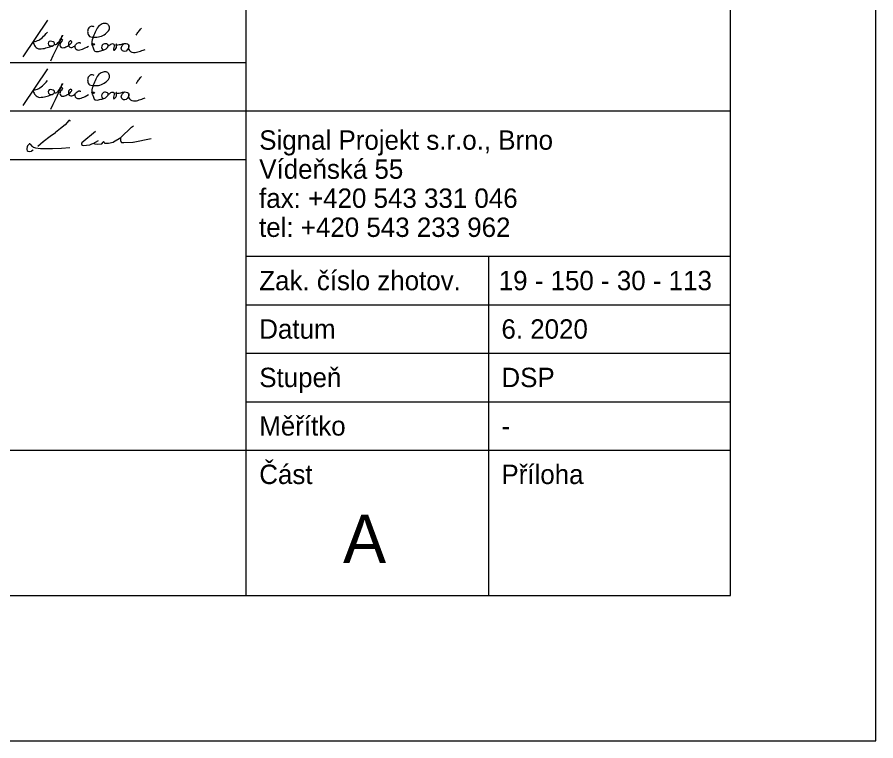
# Model space of a CAD drawing. Extents: x -790471 to -790261, y -984072 to -983775.
# Drawn here: x -790349.2 to -790260.6, y -984071.6 to -983996.9 of the extents above; entities that cross this region are included whole.
import ezdxf

# ---------------------------------------------------------------- set-up
doc = ezdxf.new("R2010")
doc.units = 0
for name, color, linetype in [('Deska žb', 7, 'Continuous'), ('Podpisy', 7, 'Continuous'), ('Ramečky', 7, 'Continuous'), ('Rámečky-tisk', 7, 'Continuous'), ('Text', 7, 'Continuous'), ('Text barevný', 7, 'Continuous')]:
    doc.layers.add(name, color=color, linetype=linetype)

# ---------------------------------------------------------------- blocks, each defined once
blk = doc.blocks.new('Lukášek')
at = {"layer": 'Deska žb'}
for points in [[(-658, 623), (-799, 512)], [(-538, 757), (-656, 625)], [(-526, 763), (-532, 761)], [(-502, 743), (-503, 750)], [(1060, 236), (1392, 554)], [(1393, 555), (1452, 601)], [(-1120, 270), (-1334, 99)], [(-949, 386), (-1119, 271)], [(-800, 511), (-947, 387)], [(277, 422), (-140, 71)], [(-1810, -20), (-1764, 37)], [(-1741, 39), (-1734, 34)], [(-1733, 32), (-1676, -31)], [(-1334, 99), (-1493, -40)], [(-146, 58), (-146, 41)], [(-146, 38), (-141, 12)], [(0, 0), (116, 16)], [(120, 17), (203, 49)], [(205, 50), (283, 92)], [(244, 59), (250, 49)], [(261, 42), (331, 30)], [(284, 93), (373, 148)], [(335, 30), (465, 39)], [(476, 45), (519, 96)], [(546, 94), (559, 68)], [(574, 60), (681, 63)], [(685, 63), (829, 98)], [(833, 100), (1057, 233)], [(1056, 231), (1056, 130)], [(1058, 121), (1075, 95)], [(1086, 88), (1147, 79)], [(1150, 79), (1434, 92)], [(1437, 93), (1997, 211)], [(-1825, -119), (-1813, -28)], [(-1809, -179), (-1825, -126)], [(-1757, -200), (-1797, -190)], [(-1700, -189), (-1749, -201)], [(-1634, -152), (-1695, -187)], [(-1672, -34), (-1636, -56)], [(-1633, -57), (-1570, -82)], [(-1567, -83), (-1418, -106)], [(-1415, -106), (-1252, -106), (-1041, -106)], [(-1040, -106), (-770, -93)], [(-769, -92), (-512, -66)], [(-127, -2), (-88, -6)], [(-85, -7), (-1, 0)]]:
    blk.add_lwpolyline(points, dxfattribs=at)
for centre, start, end in [((-669, 636), 308.3333, 317.9357), ((-525, 746), 113.9625, 137.9357), ((-519, 748), 6.3402, 113.9625), ((1403, 542), 127.875, 133.8427), ((-1110, 257), 123.9436, 128.6598), ((-958, 399), 303.9436, 310.1792), ((-789, 499), 128.3333, 130.1792), ((-1751, 26), 50.1944, 140.7106), ((-1745, 21), 41.9872, 50.1944), ((-1324, 86), 128.6598, 131.1859), ((-129, 58), 130.156, 180), ((-129, 41), 180, 189.4623), ((-125, 15), 189.4623, 262.875), ((-2, 16), 274.3987, 277.9072), ((114, 32), 277.9072, 291.0375), ((197, 64), 291.0375, 298.4429), ((264, 58), 210.9638, 260.5377), ((275, 107), 298.4429, 302.1957), ((334, 46), 260.5377, 274.0856), ((463, 55), 274.0856, 320.4403), ((531, 86), 27.8973, 140.4403), ((574, 76), 207.8973, 271.5911), ((681, 79), 271.5911, 283.7363), ((825, 114), 283.7363, 300.7189), ((1072, 130), 180, 212.4712), ((1049, 247), 300.7189, 313.8427), ((1089, 104), 212.4712, 261.8699), ((1149, 96), 261.8699, 272.6324), ((1433, 109), 272.6324, 281.9566), ((-1809, -121), 172.4054, 196.6992), ((-1797, -30), 140.7106, 172.4054), ((-1793, -175), 196.6992, 255.9638), ((-1753, -184), 255.9638, 283.2405), ((-1703, -173), 283.2405, 300.0686), ((-1664, -20), 221.9872, 239.7436), ((-1627, -41), 239.7436, 248.1986), ((-1564, -67), 248.1986, 261.3475), ((-1415, -89), 261.3475, 270), ((-1041, -89), 270, 272.7927), ((-771, -76), 272.7927, 275.856), ((-86, 10), 262.875, 274.3987)]:
    blk.add_arc(centre, 16.5, start, end, dxfattribs=at)

msp = doc.modelspace()

# ---------------------------------------------------------------- linework, layer by layer
for p, q in [((-790346.115, -983997.244), (-790348.663, -984001.025)), ((-790346.115, -984002.244), (-790348.663, -984006.025))]:
    msp.add_line(p, q)
for points in [[(-790341.279, -983997.932), (-790341.403, -983997.883), (-790341.624, -983997.795), (-790341.944, -983998.102), (-790341.988, -983998.492), (-790341.839, -983998.977), (-790341.182, -983999.004), (-790340.523, -983998.931), (-790339.963, -983998.552), (-790339.627, -983998.121), (-790339.743, -983997.755), (-790340.022, -983997.524), (-790340.448, -983997.591), (-790340.922, -983997.862), (-790341.175, -983998.482), (-790341.471, -983999.088), (-790341.534, -983999.538), (-790341.56, -983999.725)], [(-790336.941, -983998.767), (-790336.885, -983998.674), (-790336.731, -983998.417), (-790336.529, -983998.195), (-790336.4, -983998.053)], [(-790347.607, -983999.459), (-790347.471, -983999.438), (-790347.152, -983999.39), (-790346.617, -983999.051), (-790346.31, -983998.682), (-790346.12, -983998.454)], [(-790345.367, -983999.701), (-790345.331, -983999.727), (-790345.071, -983999.918), (-790344.193, -983997.983), (-790345.101, -983999.96), (-790345.793, -984001.466)], [(-790347.607, -983999.459), (-790347.564, -983999.581), (-790347.469, -983999.848), (-790347.105, -984000.265), (-790346.386, -984000.146), (-790345.871, -983999.982), (-790345.36, -983999.82), (-790345.358, -983999.503), (-790345.652, -983999.408), (-790345.966, -983999.372), (-790346.085, -983999.642), (-790345.908, -983999.896), (-790345.702, -983999.894), (-790345.586, -983999.893)], [(-790344.735, -983999.177), (-790344.686, -983999.177), (-790344.387, -983999.177), (-790344.935, -983999.693), (-790344.696, -984000.168), (-790344.167, -983999.993), (-790343.885, -983999.83), (-790343.466, -983999.455), (-790343.798, -983999.276), (-790344.006, -983999.671), (-790343.862, -984000.105), (-790343.352, -983999.997), (-790343.146, -983999.688), (-790342.94, -983999.53), (-790342.757, -983999.518), (-790342.732, -983999.588), (-790342.716, -983999.63)], [(-790343.286, -983999.868), (-790343.285, -983999.962), (-790343.284, -984000.133), (-790343.045, -984000.359), (-790342.5, -984000.261), (-790342.128, -984000.055), (-790341.867, -983999.911)], [(-790341.56, -983999.725), (-790341.52, -983999.687), (-790341.438, -983999.606), (-790341.14, -983999.722), (-790341.419, -983999.825), (-790341.509, -983999.807), (-790341.521, -983999.804)], [(-790341.521, -983999.804), (-790341.474, -983999.87), (-790341.357, -984000.031), (-790341.303, -984000.538), (-790340.687, -984000.428), (-790340.261, -984000.313), (-790339.98, -984000.166), (-790339.692, -983999.742), (-790340.293, -983999.598), (-790340.517, -983999.901), (-790340.533, -984000.2), (-790340.397, -984000.281), (-790340.337, -984000.317)], [(-790339.858, -983999.773), (-790339.824, -983999.81), (-790339.761, -983999.877), (-790339.618, -983999.774), (-790339.527, -983999.643), (-790339.088, -983999.646), (-790339.415, -984000.465), (-790338.967, -984000.238), (-790338.963, -983999.549), (-790339.087, -983999.805), (-790339.029, -983999.851), (-790338.865, -983999.772), (-790338.538, -983999.749), (-790338.168, -983999.582), (-790337.514, -983999.74), (-790337.986, -984000.599), (-790338.522, -984000.346), (-790338.486, -983999.912), (-790338.288, -983999.74), (-790338.187, -983999.652)], [(-790337.732, -983999.834), (-790337.744, -984000.022), (-790337.77, -984000.434), (-790337.02, -984000.633), (-790336.498, -984000.411), (-790336.141, -984000.288), (-790336.021, -984000.247)], [(-790341.279, -984002.932), (-790341.403, -984002.883), (-790341.624, -984002.795), (-790341.944, -984003.102), (-790341.988, -984003.492), (-790341.839, -984003.977), (-790341.182, -984004.004), (-790340.523, -984003.931), (-790339.963, -984003.552), (-790339.627, -984003.121), (-790339.743, -984002.755), (-790340.022, -984002.524), (-790340.448, -984002.591), (-790340.922, -984002.862), (-790341.175, -984003.482), (-790341.471, -984004.088), (-790341.534, -984004.538), (-790341.56, -984004.725)], [(-790347.607, -984004.459), (-790347.471, -984004.438), (-790347.152, -984004.39), (-790346.617, -984004.051), (-790346.31, -984003.682), (-790346.12, -984003.454)], [(-790336.941, -984003.767), (-790336.885, -984003.674), (-790336.731, -984003.417), (-790336.529, -984003.195), (-790336.4, -984003.053)], [(-790347.607, -984004.459), (-790347.564, -984004.581), (-790347.469, -984004.848), (-790347.105, -984005.265), (-790346.386, -984005.146), (-790345.871, -984004.982), (-790345.36, -984004.82), (-790345.358, -984004.503), (-790345.652, -984004.408), (-790345.966, -984004.372), (-790346.085, -984004.642), (-790345.908, -984004.896), (-790345.702, -984004.894), (-790345.586, -984004.893)], [(-790345.367, -984004.701), (-790345.331, -984004.727), (-790345.071, -984004.918), (-790344.193, -984002.983), (-790345.101, -984004.96), (-790345.793, -984006.466)], [(-790344.735, -984004.177), (-790344.686, -984004.177), (-790344.387, -984004.177), (-790344.935, -984004.693), (-790344.696, -984005.168), (-790344.167, -984004.993), (-790343.885, -984004.83), (-790343.466, -984004.455), (-790343.798, -984004.276), (-790344.006, -984004.671), (-790343.862, -984005.105), (-790343.352, -984004.997), (-790343.146, -984004.688), (-790342.94, -984004.53), (-790342.757, -984004.518), (-790342.732, -984004.588), (-790342.716, -984004.63)], [(-790343.286, -984004.868), (-790343.285, -984004.962), (-790343.284, -984005.133), (-790343.045, -984005.359), (-790342.5, -984005.261), (-790342.128, -984005.055), (-790341.867, -984004.911)], [(-790341.56, -984004.725), (-790341.52, -984004.687), (-790341.438, -984004.606), (-790341.14, -984004.722), (-790341.419, -984004.825), (-790341.509, -984004.807), (-790341.521, -984004.804)], [(-790341.521, -984004.804), (-790341.474, -984004.87), (-790341.357, -984005.031), (-790341.303, -984005.538), (-790340.687, -984005.428), (-790340.261, -984005.313), (-790339.98, -984005.166), (-790339.692, -984004.742), (-790340.293, -984004.598), (-790340.517, -984004.901), (-790340.533, -984005.2), (-790340.397, -984005.281), (-790340.337, -984005.317)], [(-790339.858, -984004.773), (-790339.824, -984004.81), (-790339.761, -984004.877), (-790339.618, -984004.774), (-790339.527, -984004.643), (-790339.088, -984004.646), (-790339.415, -984005.465), (-790338.967, -984005.238), (-790338.963, -984004.549), (-790339.087, -984004.805), (-790339.029, -984004.851), (-790338.865, -984004.772), (-790338.538, -984004.749), (-790338.168, -984004.582), (-790337.514, -984004.74), (-790337.986, -984005.599), (-790338.522, -984005.346), (-790338.486, -984004.912), (-790338.288, -984004.74), (-790338.187, -984004.652)], [(-790337.732, -984004.834), (-790337.744, -984005.022), (-790337.77, -984005.434), (-790337.02, -984005.633), (-790336.498, -984005.411), (-790336.141, -984005.288), (-790336.021, -984005.247)]]:
    msp.add_open_spline(points, degree=3)
at = {"layer": 'Ramečky'}
for p, q in [((-790325.592, -984056.601), (-790325.592, -983971.601)), ((-790275.592, -984056.601), (-790275.592, -983971.601)), ((-790455.592, -984001.601), (-790325.592, -984001.601)), ((-790455.592, -984006.601), (-790325.592, -984006.601)), ((-790455.592, -984011.601), (-790325.592, -984011.601)), ((-790325.592, -984021.601), (-790275.592, -984021.601)), ((-790325.592, -984026.601), (-790275.592, -984026.601)), ((-790325.592, -984031.601), (-790275.592, -984031.601)), ((-790325.592, -984036.601), (-790275.592, -984036.601)), ((-790455.592, -984041.601), (-790275.592, -984041.601)), ((-790455.592, -984056.601), (-790275.592, -984056.601))]:
    msp.add_line(p, q, dxfattribs=at)
for points in [[(-790325.592, -984006.601), (-790275.592, -984006.601)], [(-790300.592, -984021.601), (-790300.592, -984056.601)]]:
    msp.add_lwpolyline(points, dxfattribs=at)
at = {"layer": 'Rámečky-tisk'}
msp.add_lwpolyline([(-790470.592, -984071.601), (-790260.592, -984071.601), (-790260.592, -983774.601)], dxfattribs=at)

# ---------------------------------------------------------------- block references
at = {"layer": 'Podpisy', "xscale": 0.0033510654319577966, "yscale": 0.0033510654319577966}
msp.add_blockref('Lukášek', (-790342.091, -984010.135), dxfattribs=at)

# ---------------------------------------------------------------- texts
at = {"layer": 'Text'}
for s, p in [('Signal Projekt s.r.o., Brno', (-790324.243, -984010.601)), ('Vídeňská 55', (-790324.243, -984013.601)), ('fax: +420 543 331 046', (-790324.261, -984016.601)), ('tel: +420 543 233 962', (-790324.261, -984019.601)), ('Zak. číslo zhotov.', (-790324.242, -984025.101)), ('19 - 150 - 30 - 113', (-790299.52, -984025.101)), ('Datum', (-790324.242, -984030.101)), ('6. 2020', (-790299.242, -984030.101)), ('Stupeň', (-790324.242, -984035.101)), ('DSP', (-790299.242, -984035.101)), ('Měřítko', (-790324.242, -984040.101)), ('-', (-790299.242, -984040.101)), ('Část', (-790324.242, -984045.101)), ('Příloha', (-790299.242, -984045.101))]:
    msp.add_text(s, height=2, dxfattribs=at).set_placement(p)
at = {"layer": 'Text barevný'}
msp.add_text('A', height=5, dxfattribs=at).set_placement((-790315.6, -984053.267))

doc.saveas('drawing.dxf')
